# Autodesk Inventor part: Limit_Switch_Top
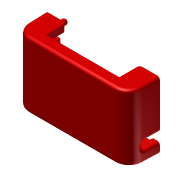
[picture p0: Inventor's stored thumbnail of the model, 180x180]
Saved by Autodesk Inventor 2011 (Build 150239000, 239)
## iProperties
Created: 2010-04
Part Number: Limit_Switch_Top
Document SubType Name: Modeling
Designer: Phil
Density: 1.06 g/cm^3
Material: ABS Plastic
Mass: 2.23104 g
Surface Area: 23.0657 cm^2
Volume: 2.10476 cm^3
Author: Phil
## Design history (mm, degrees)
sketch "Sketch1"
  geometry: L1 (-167.58, -125.8)-(-135.932, -125.8); L2 (-135.932, -125.8)-(-135.932, -107.309); L3 (-135.932, -107.309)-(-167.58, -107.309); L4 (-167.58, -107.309)-(-167.58, -125.8)
  constraints: 8 end point, 2 parallel, 1 horizontal, 1 perpendicular
  dimensions: "d4" = 31.6484 distance of L3.end L2.end; "d5" = 18.4912 distance of L2.end L1.end
extrude "Extrusion1" new body sketch "Sketch1" distance "d6" = 8.5598; taper "d7" = -1 deg
fillet "Fillet1" dims "d8" = 3.81
sketch "Sketch2"
  geometry: L1 (167.58, -125.8)-(135.932, -125.8) reference; L2 (167.58, -107.309)-(167.58, -125.8) reference; L3 (135.932, -107.309)-(167.58, -107.309) reference; L4 (135.932, -125.8)-(135.932, -107.309) reference; L5 (137.989, -123.743)-(165.523, -123.743); L6 (165.523, -123.743)-(165.523, -116.758); L7 (165.523, -116.758)-(163.465, -116.758); L8 (163.465, -116.758)-(163.465, -111.805); L9 (163.465, -111.805)-(165.523, -111.805); L10 (165.523, -111.805)-(165.523, -109.366); L11 (165.523, -109.366)-(137.989, -109.366); L12 (137.989, -109.366)-(137.989, -111.805); L13 (137.989, -111.805)-(140.047, -111.805); L14 (140.047, -111.805)-(140.047, -116.758); L15 (140.047, -116.758)-(137.989, -116.758); L16 (137.989, -116.758)-(137.989, -123.743); 3 further points
  constraints: 24 end point, 8 parallel, 6 collinear, 3 perpendicular, 2 midpoint, 1 vertical alignment
  dimensions: "d9" = 2.0574 distance between parallel lines of L11 L3; "d10" = 2.4384 distance of L9.end L10.end; "d11" = 4.953 distance of L7.end L8.end; "d12" = 2.0574 distance between parallel lines of L6 L2 (= d9); "d13" = 2.0574 distance between parallel lines of L5 L1 (= d9); "d14" = 2.0574 distance between parallel lines of L8 L6 (= d9)
extrude "Extrusion2" cut sketch "Sketch2" distance "d15" = 6.5532; taper "d16" = 0 deg
sketch "Sketch3"
  geometry: L1 (137.989, -123.743)-(137.989, -116.758) reference; L2 (167.58, -125.8)-(135.932, -125.8) reference; L3 (135.932, -125.8)-(135.932, -107.309) reference; L4 (137.989, -122.905)-(135.932, -122.905); L5 (135.932, -120.517)-(137.989, -120.517); 1 further point
  constraints: 4 end point, 4 point on line, 1 parallel, 1 perpendicular
  dimensions: "d17" = 2.8956 distance between parallel lines of L4 L2; "d18" = 2.3876 distance between parallel lines of L5 L4
extrude "Extrusion3" cut sketch "Sketch3" distance "d19" = 4.699; taper "d20" = 0 deg
sketch "Sketch4"
  geometry: L1 (31.648, 0)-(31.564, -4.817) reference; L2 (31.648, 0)-(0, 0) reference; L3 (0, 0)-(0.084, -4.817) reference; L4 (3.893, -8.561)-(27.755, -8.561) reference; L5 (26.056, 0)-(25.959, -5.563); L6 (25.959, -5.563)-(5.69, -5.563); L7 (5.69, -5.563)-(5.593, 0); 3 further points
  constraints: 6 end point, 3 parallel, 2 midpoint, 2 point on line, 1 vertical alignment
  dimensions: "d21" = 20.2692 distance of L5.end L6.end; "d22" = 5.5626 distance between parallel lines of L2 L6
extrude "Extrusion4" cut sketch "Sketch4" stored distance "d23" = 4.699; taper "d24" = 0 deg
sketch "Sketch5"
  geometry: L1 (140.047, -116.758)-(140.047, -111.805) reference; L2 (163.465, -111.805)-(163.465, -116.758) reference; 4 further points
  constraints: 2 midpoint
hole "Hole1" sketch "Sketch5" at (140.047, -114.281), (163.465, -114.281), (190.715, -140.083) diameter "d25" = 1.8542; stored, may be unused: countersink angle "d29" = 82 deg, drill point angle "d31" = 0 deg; dims "d26" = 19.05, "d27" = 2.8956, "d28" = 6.35, "d30" = 25.4
sketch "Sketch6"
  geometry: L1 (135.932, -125.8)-(135.932, -122.905) reference; L2 (167.58, -125.8)-(135.932, -125.8) reference; L3 (167.58, -107.309)-(167.58, -125.8) reference; L4 (161.988, -107.309)-(167.58, -107.309) reference; C1 r 0.749 at (138.751, -124.81); C2 r 0.749 at (163.364, -108.3); 1 further point
  constraints: 2 centre point
  dimensions: "d32" = 1.4986 diameter of C1; "d33" = 2.8194 distance from line of L1 C1.centre; "d34" = 0.9906 distance from line of L2 C1.centre; "d35" = 4.2164 distance from line of L3 C2.centre; "d36" = 0.9906 distance from line of L4 C2.centre; "d37" = 1.4986 diameter of C2
extrude "Extrusion5" join sketch "Sketch6" distance "d38" = 1.4986; taper "d39" = 0 deg
fillet "Fillet2" dims "d40" = 0.635
fillet "Fillet3" dims "d41" = 0.7874
fillet "Fillet4" dims "d42" = 0.762
fillet "Fillet5" dims "d43" = 1.524
fillet "Fillet6" dims "d44" = 0.5334
fillet "Fillet7" dims "d45" = 0.254, "d46" = 0.762
fillet "Fillet8" dims "d47" = 0.762
body "Solid1"
